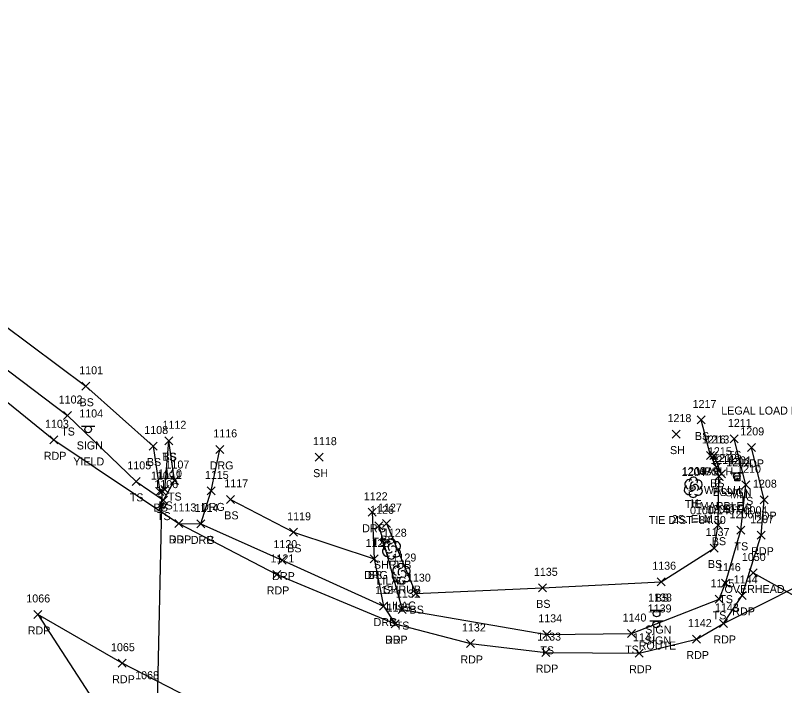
# Model space of a CAD drawing. Extents: x 1611797 to 1633212, y 298978 to 305475.
# Drawn here: x 1612037.9 to 1612230.1, y 300494.1 to 300661.6 of the extents above; entities that cross this region are included whole.
import ezdxf

# ---------------------------------------------------------------- set-up
doc = ezdxf.new("R2010")
doc.units = 0
for name, color, linetype in [('C_A', 7, 'Continuous'), ('C_C', 7, 'Continuous'), ('C_I', 7, 'Continuous'), ('CBP', 7, 'Continuous'), ('D_A', 7, 'Continuous'), ('D_C', 7, 'Continuous'), ('D_I', 7, 'Continuous'), ('D_TIC', 7, 'Continuous'), ('DCP', 7, 'Continuous'), ('DHW', 7, 'Continuous'), ('L_A', 7, 'Continuous'), ('L_C', 7, 'Continuous'), ('L_I', 7, 'Continuous'), ('L_TIC', 7, 'Continuous'), ('LELB', 7, 'Continuous'), ('LSH', 7, 'Continuous'), ('LTD', 7, 'Continuous'), ('P_A', 7, 'Continuous'), ('P_I', 7, 'Continuous'), ('P_TIC', 7, 'Continuous'), ('PET', 7, 'Continuous'), ('R_A', 7, 'Continuous'), ('R_I', 7, 'Continuous'), ('R_TIC', 7, 'Continuous'), ('RDG', 7, 'Continuous'), ('RDP', 7, 'Continuous'), ('S_A', 7, 'Continuous'), ('S_C', 7, 'Continuous'), ('S_I', 7, 'Continuous'), ('SRM', 7, 'Continuous'), ('SSGN', 7, 'Continuous'), ('U_A', 7, 'Continuous'), ('U_I', 7, 'Continuous'), ('U_TIC', 7, 'Continuous'), ('UCO', 7, 'Continuous')]:
    doc.layers.add(name, color=color, linetype=linetype)

msp = doc.modelspace()

# ---------------------------------------------------------------- linework, layer by layer
at = {"layer": 'CBP'}
for radius in [0.625, 0.0833]:
    msp.add_circle((1612207.07, 300543.45), radius, dxfattribs=at)
at = {"layer": 'D_TIC'}
for points in [[(1612211.41, 300550.59), (1612213.41, 300552.59)], [(1612213.41, 300550.59), (1612211.41, 300552.59)], [(1612212.03, 300547.65), (1612214.03, 300549.65)], [(1612214.03, 300547.65), (1612212.03, 300549.65)], [(1612213.3, 300545.96), (1612215.3, 300547.96)], [(1612215.3, 300545.96), (1612213.3, 300547.96)], [(1612073.52, 300541.7), (1612075.52, 300543.7)], [(1612075.52, 300541.7), (1612073.52, 300543.7)]]:
    msp.add_lwpolyline(points, dxfattribs=at)
at = {"layer": 'DCP'}
msp.add_lwpolyline([(1612073.27, 300485.68), (1612074.52, 300542.7)], dxfattribs=at)
at = {"layer": 'DHW'}
msp.add_lwpolyline([(1612214.3, 300546.96), (1612212.41, 300551.59)], dxfattribs=at)
at = {"layer": 'L_TIC'}
for points in [[(1612054.46, 300567.89), (1612056.46, 300569.89)], [(1612056.46, 300567.89), (1612054.46, 300569.89)], [(1612049.89, 300560.58), (1612051.89, 300562.58)], [(1612051.89, 300560.58), (1612049.89, 300562.58)], [(1612208.2, 300559.46), (1612210.2, 300561.46)], [(1612210.2, 300559.46), (1612208.2, 300561.46)], [(1612201.93, 300555.93), (1612203.93, 300557.93)], [(1612203.93, 300555.93), (1612201.93, 300557.93)], [(1612071.28, 300552.95), (1612073.28, 300554.95)], [(1612073.28, 300552.95), (1612071.28, 300554.95)], [(1612075.19, 300554.26), (1612077.19, 300556.26)], [(1612077.19, 300554.26), (1612075.19, 300556.26)], [(1612075.19, 300554.26), (1612077.19, 300556.26)], [(1612077.19, 300554.26), (1612075.19, 300556.26)], [(1612216.45, 300554.73), (1612218.45, 300556.73)], [(1612218.45, 300554.73), (1612216.45, 300556.73)], [(1612112.78, 300550.17), (1612114.78, 300552.17)], [(1612114.78, 300550.17), (1612112.78, 300552.17)], [(1612210.57, 300550.59), (1612212.57, 300552.59)], [(1612212.57, 300550.59), (1612210.57, 300552.59)], [(1612212.03, 300547.65), (1612214.03, 300549.65)], [(1612214.03, 300547.65), (1612212.03, 300549.65)], [(1612212.64, 300545.45), (1612214.64, 300547.45)], [(1612214.64, 300545.45), (1612212.64, 300547.45)], [(1612067.05, 300544.12), (1612069.05, 300546.12)], [(1612069.05, 300544.12), (1612067.05, 300546.12)], [(1612076.59, 300544.32), (1612078.59, 300546.32)], [(1612078.59, 300544.32), (1612076.59, 300546.32)], [(1612072.95, 300541.57), (1612074.95, 300543.57)], [(1612074.95, 300541.57), (1612072.95, 300543.57)], [(1612074.18, 300542.1), (1612076.18, 300544.1)], [(1612076.18, 300542.1), (1612074.18, 300544.1)], [(1612219.41, 300543.25), (1612221.41, 300545.25)], [(1612221.41, 300543.25), (1612219.41, 300545.25)], [(1612090.62, 300539.62), (1612092.62, 300541.62)], [(1612092.62, 300539.62), (1612090.62, 300541.62)], [(1612073.84, 300539.42), (1612075.84, 300541.42)], [(1612075.84, 300539.42), (1612073.84, 300541.42)], [(1612127.68, 300533), (1612129.68, 300535)], [(1612129.68, 300533), (1612127.68, 300535)], [(1612129.59, 300533.56), (1612131.59, 300535.56)], [(1612131.59, 300533.56), (1612129.59, 300535.56)], [(1612212.42, 300533.16), (1612214.42, 300535.16)], [(1612214.42, 300533.16), (1612212.42, 300535.16)], [(1612218.14, 300531.88), (1612220.14, 300533.88)], [(1612220.14, 300531.88), (1612218.14, 300533.88)], [(1612106.35, 300531.38), (1612108.35, 300533.38)], [(1612108.35, 300531.38), (1612106.35, 300533.38)], [(1612211.46, 300527.45), (1612213.46, 300529.45)], [(1612213.46, 300527.45), (1612211.46, 300529.45)], [(1612126.5, 300524.71), (1612128.5, 300526.71)], [(1612128.5, 300524.71), (1612126.5, 300526.71)], [(1612198.18, 300519.03), (1612200.18, 300521.03)], [(1612200.18, 300519.03), (1612198.18, 300521.03)], [(1612214.33, 300518.67), (1612216.33, 300520.67)], [(1612216.33, 300518.67), (1612214.33, 300520.67)], [(1612168.55, 300517.5), (1612170.55, 300519.5)], [(1612170.55, 300517.5), (1612168.55, 300519.5)], [(1612136.91, 300516.05), (1612138.91, 300518.05)], [(1612138.91, 300516.05), (1612136.91, 300518.05)], [(1612212.69, 300514.63), (1612214.69, 300516.63)], [(1612214.69, 300514.63), (1612212.69, 300516.63)], [(1612133.5, 300512.07), (1612135.5, 300514.07)], [(1612135.5, 300512.07), (1612133.5, 300514.07)], [(1612169.63, 300505.87), (1612171.63, 300507.87)], [(1612171.63, 300505.87), (1612169.63, 300507.87)], [(1612190.79, 300506.07), (1612192.79, 300508.07)], [(1612192.79, 300506.07), (1612190.79, 300508.07)]]:
    msp.add_lwpolyline(points, dxfattribs=at)
at = {"layer": 'LELB'}
for points in [[(1611964.04, 300661.61), (1611970.26, 300646.34), (1611994.83, 300618.41), (1612027.74, 300589.61), (1612055.46, 300568.89), (1612072.28, 300553.95), (1612073.95, 300542.57), (1612075.18, 300543.1), (1612076.19, 300555.26)], [(1611953.6, 300656.36), (1611964.8, 300638.56), (1611988.71, 300611.02), (1612021.99, 300583.42), (1612050.89, 300561.58), (1612068.05, 300545.12), (1612074.84, 300540.42), (1612077.59, 300545.32), (1612076.19, 300555.26)], [(1612130.59, 300534.56), (1612137.91, 300517.05), (1612169.55, 300518.5), (1612199.18, 300520.03), (1612212.46, 300528.45), (1612213.42, 300534.16), (1612213.64, 300546.45), (1612213.03, 300548.65), (1612211.57, 300551.59), (1612209.2, 300560.46)], [(1612128.68, 300534), (1612134.5, 300513.07), (1612170.63, 300506.87), (1612191.79, 300507.07), (1612213.69, 300515.63), (1612215.33, 300519.67), (1612219.14, 300532.88), (1612220.41, 300544.25), (1612217.45, 300555.73)], [(1612091.62, 300540.62), (1612107.35, 300532.38), (1612127.5, 300525.71)]]:
    msp.add_lwpolyline(points, dxfattribs=at)
at = {"layer": 'LSH'}
for p, q in [((1612131.81, 300528.28), (1612131.81, 300528.28)), ((1612131.81, 300528.28), (1612131.81, 300528.28)), ((1612134.22, 300522.08), (1612134.22, 300522.08)), ((1612134.22, 300522.08), (1612134.22, 300522.08))]:
    msp.add_line(p, q, dxfattribs=at)
for centre in [(1612131.86, 300529.71), (1612134.27, 300523.51)]:
    msp.add_arc(centre, 1.05, 335.5272, 180.9563, dxfattribs=at)
for centre, major_axis, ratio, start_param, end_param in [((1612131.02, 300528.94), (1.21, -0.51), 0.895232, 1.570796, 4.712389), ((1612132.85, 300528.86), (-1.14, -0.48), 0.949671, 1.570796, 4.712389), ((1612130.73, 300527.57), (0.58, -1.04), 0.959034, 3.141593, 6.283185), ((1612131.6, 300528.73), (-0.208, -0.792), 0.645439, 3.141593, 6.283185), ((1612132.31, 300528.11), (-0.5, 0.667), 0.989748, 3.141593, 6.283185), ((1612132.81, 300527.44), (-1.09, 0.79), 0.841452, 1.570796, 4.712389), ((1612131.81, 300526.78), (0.26, 1.06), 0.942809, 1.570796, 4.712389), ((1612131.35, 300527.53), (-0.625, -0.083), 0.423636, 0, 3.141593), ((1612133.14, 300521.37), (0.58, -1.04), 0.959034, 3.141593, 6.283185), ((1612133.43, 300522.75), (1.21, -0.51), 0.895232, 1.570796, 4.712389), ((1612134.02, 300522.54), (-0.208, -0.792), 0.645439, 3.141593, 6.283185), ((1612134.72, 300521.91), (-0.5, 0.667), 0.989748, 3.141593, 6.283185), ((1612135.27, 300522.66), (-1.14, -0.48), 0.949671, 1.570796, 4.712389), ((1612134.22, 300520.58), (0.26, 1.06), 0.942809, 1.570796, 4.712389), ((1612133.77, 300521.33), (-0.625, -0.083), 0.423636, 0, 3.141593), ((1612135.22, 300521.25), (-1.09, 0.79), 0.841452, 1.570796, 4.712389)]:
    msp.add_ellipse(centre, major_axis=major_axis, ratio=ratio, start_param=start_param, end_param=end_param, dxfattribs=at)
at = {"layer": 'LTD'}
msp.add_line((1612207.23, 300543.69), (1612207.23, 300543.69), dxfattribs=at)
msp.add_line((1612207.23, 300543.69), (1612207.23, 300543.69), dxfattribs=at)
msp.add_arc((1612207.28, 300545.12), 1.05, 335.5272, 180.9563, dxfattribs=at)
for centre, major_axis, ratio, start_param, end_param in [((1612206.44, 300544.35), (1.21, -0.51), 0.895232, 1.570796, 4.712389), ((1612208.27, 300544.27), (-1.14, -0.48), 0.949671, 1.570796, 4.712389), ((1612206.15, 300542.98), (0.58, -1.04), 0.959034, 3.141593, 6.283185), ((1612207.02, 300544.14), (-0.208, -0.792), 0.645439, 3.141593, 6.283185), ((1612207.73, 300543.52), (-0.5, 0.667), 0.989748, 3.141593, 6.283185), ((1612208.23, 300542.85), (-1.09, 0.79), 0.841452, 1.570796, 4.712389), ((1612207.23, 300542.19), (0.26, 1.06), 0.942809, 1.570796, 4.712389), ((1612206.77, 300542.94), (-0.625, -0.083), 0.423636, 0, 3.141593)]:
    msp.add_ellipse(centre, major_axis=major_axis, ratio=ratio, start_param=start_param, end_param=end_param, dxfattribs=at)
at = {"layer": 'P_TIC'}
for points in [[(1612046.48, 300554.5), (1612048.48, 300556.5)], [(1612048.48, 300554.5), (1612046.48, 300556.5)], [(1612220.78, 300552.61), (1612222.78, 300554.61)], [(1612222.78, 300552.61), (1612220.78, 300554.61)], [(1612223.94, 300539.54), (1612225.94, 300541.54)], [(1612225.94, 300539.54), (1612223.94, 300541.54)], [(1612077.69, 300533.59), (1612079.69, 300535.59)], [(1612079.69, 300533.59), (1612077.69, 300535.59)], [(1612223.22, 300530.66), (1612225.22, 300532.66)], [(1612225.22, 300530.66), (1612223.22, 300532.66)], [(1612102.17, 300520.85), (1612104.17, 300522.85)], [(1612104.17, 300520.85), (1612102.17, 300522.85)], [(1612218.49, 300515.61), (1612220.49, 300517.61)], [(1612220.49, 300515.61), (1612218.49, 300517.61)], [(1612042.48, 300510.85), (1612044.48, 300512.85)], [(1612044.48, 300510.85), (1612042.48, 300512.85)], [(1612131.73, 300508.54), (1612133.73, 300510.54)], [(1612133.73, 300508.54), (1612131.73, 300510.54)], [(1612213.78, 300508.59), (1612215.78, 300510.59)], [(1612215.78, 300508.59), (1612213.78, 300510.59)], [(1612213.78, 300508.59), (1612215.78, 300510.59)], [(1612215.78, 300508.59), (1612213.78, 300510.59)], [(1612150.57, 300503.59), (1612152.57, 300505.59)], [(1612152.57, 300503.59), (1612150.57, 300505.59)], [(1612207.02, 300504.7), (1612209.02, 300506.7)], [(1612209.02, 300504.7), (1612207.02, 300506.7)], [(1612169.38, 300501.31), (1612171.38, 300503.31)], [(1612171.38, 300501.31), (1612169.38, 300503.31)], [(1612192.74, 300501.14), (1612194.74, 300503.14)], [(1612194.74, 300501.14), (1612192.74, 300503.14)], [(1612063.58, 300498.66), (1612065.58, 300500.66)], [(1612065.58, 300498.66), (1612063.58, 300500.66)]]:
    msp.add_lwpolyline(points, dxfattribs=at)
at = {"layer": 'PET'}
for points in [[(1611938.88, 300643.49), (1611961.36, 300631.75), (1611984.86, 300608.51), (1612017.32, 300579.9), (1612047.48, 300555.5), (1612078.69, 300534.59), (1612103.17, 300521.85), (1612132.73, 300509.54), (1612151.57, 300504.59), (1612170.38, 300502.31), (1612193.74, 300502.14), (1612208.02, 300505.7), (1612214.78, 300509.59), (1612242.88, 300523.72)], [(1612214.78, 300509.59), (1612219.49, 300516.61), (1612224.22, 300531.66), (1612224.94, 300540.54), (1612221.78, 300553.61)], [(1612081.39, 300452.17), (1612099.61, 300458.97), (1612131.48, 300469.92), (1612112.83, 300476.98), (1612089.93, 300486.55), (1612064.58, 300499.66), (1612043.48, 300511.85), (1612066.24, 300476.74)]]:
    msp.add_lwpolyline(points, dxfattribs=at)
at = {"layer": 'R_TIC'}
for points in [[(1612087.93, 300552.11), (1612089.93, 300554.11)], [(1612089.93, 300552.11), (1612087.93, 300554.11)], [(1612085.76, 300541.73), (1612087.76, 300543.73)], [(1612087.76, 300541.73), (1612085.76, 300543.73)], [(1612126.03, 300536.39), (1612128.03, 300538.39)], [(1612128.03, 300536.39), (1612126.03, 300538.39)], [(1612077.69, 300533.59), (1612079.69, 300535.59)], [(1612079.69, 300533.59), (1612077.69, 300535.59)], [(1612083.22, 300533.48), (1612085.22, 300535.48)], [(1612085.22, 300533.48), (1612083.22, 300535.48)], [(1612083.22, 300533.48), (1612085.22, 300535.48)], [(1612085.22, 300533.48), (1612083.22, 300535.48)], [(1612103.55, 300524.42), (1612105.55, 300526.42)], [(1612105.55, 300524.42), (1612103.55, 300526.42)], [(1612126.5, 300524.71), (1612128.5, 300526.71)], [(1612128.5, 300524.71), (1612126.5, 300526.71)], [(1612128.88, 300512.92), (1612130.88, 300514.92)], [(1612130.88, 300512.92), (1612128.88, 300514.92)], [(1612128.88, 300512.92), (1612130.88, 300514.92)], [(1612130.88, 300512.92), (1612128.88, 300514.92)], [(1612131.73, 300508.54), (1612133.73, 300510.54)], [(1612133.73, 300508.54), (1612131.73, 300510.54)]]:
    msp.add_lwpolyline(points, dxfattribs=at)
at = {"layer": 'RDG'}
for points in [[(1612084.22, 300534.48), (1612086.76, 300542.73), (1612088.93, 300553.11)], [(1612127.03, 300537.39), (1612127.5, 300525.71), (1612129.88, 300513.92)]]:
    msp.add_lwpolyline(points, dxfattribs=at)
at = {"layer": 'RDP'}
msp.add_lwpolyline([(1612078.69, 300534.59), (1612084.22, 300534.48), (1612104.55, 300525.42), (1612129.88, 300513.92), (1612132.73, 300509.54)], dxfattribs=at)
at = {"layer": 'SRM'}
msp.add_lwpolyline([(1612217.61, 300546.51), (1612218.86, 300546.51), (1612218.86, 300545.26), (1612217.61, 300545.26)], close=True, dxfattribs=at)
msp.add_circle((1612218.24, 300545.88), 0.0833, dxfattribs=at)
at = {"layer": 'SSGN'}
for p, q in [((1612054.41, 300558.95), (1612057.75, 300558.95)), ((1612056.06, 300558.12), (1612056.06, 300558.12)), ((1612216.48, 300547.22), (1612219.81, 300547.22)), ((1612218.13, 300546.39), (1612218.13, 300546.39)), ((1612196.45, 300512.94), (1612199.78, 300512.94)), ((1612198.09, 300512.1), (1612198.09, 300512.1)), ((1612196.36, 300510.21), (1612199.7, 300510.21)), ((1612198.01, 300509.37), (1612198.01, 300509.37))]:
    msp.add_line(p, q, dxfattribs=at)
for centre in [(1612056.06, 300558.12), (1612218.13, 300546.39), (1612198.09, 300512.1), (1612198.01, 300509.37)]:
    msp.add_circle(centre, 0.833, dxfattribs=at)
at = {"layer": 'U_TIC'}
for points in [[(1612221.24, 300521.21), (1612223.24, 300523.21)], [(1612223.24, 300521.21), (1612221.24, 300523.21)]]:
    msp.add_lwpolyline(points, dxfattribs=at)
at = {"layer": 'UCO'}
msp.add_lwpolyline([(1612222.24, 300522.21), (1612272.65, 300494.16)], dxfattribs=at)

# ---------------------------------------------------------------- texts
at = {"layer": 'C_A'}
msp.add_text('TIE', height=2, dxfattribs=at).set_placement((1612205.15, 300538.45))
at = {"layer": 'C_C'}
msp.add_text('TIE DIST=84.50', height=2, dxfattribs=at).set_placement((1612196.12, 300534.45))
at = {"layer": 'C_I'}
msp.add_text('1204', height=2, dxfattribs=at).set_placement((1612204.3, 300546.45))
at = {"layer": 'D_A'}
for s, p in [('WALLH', (1612208, 300546.59)), ('P', (1612212.41, 300543.65)), ('WALLH', (1612209.89, 300541.96)), ('P', (1612073.9, 300537.7))]:
    msp.add_text(s, height=2, dxfattribs=at).set_placement(p)
at = {"layer": 'D_C'}
msp.add_text('MARBLE', height=2, dxfattribs=at).set_placement((1612208.85, 300537.96))
at = {"layer": 'D_I'}
for s, p in [('1213', (1612210.29, 300554.59)), ('1215', (1612210.9, 300551.65)), ('1212', (1612212.17, 300549.96)), ('1111', (1612073.53, 300545.7))]:
    msp.add_text(s, height=2, dxfattribs=at).set_placement(p)
at = {"layer": 'L_A'}
for s, p in [('BS', (1612053.9, 300563.89)), ('TS', (1612049.3, 300556.58)), ('BS', (1612207.64, 300555.46)), ('SH', (1612201.42, 300551.93)), ('TS', (1612074.6, 300550.26)), ('BS', (1612074.63, 300550.26)), ('TS', (1612215.86, 300550.73)), ('BS', (1612070.72, 300548.95)), ('SH', (1612112.27, 300546.17)), ('BS', (1612210.01, 300546.59)), ('BS', (1612211.47, 300543.65)), ('BS', (1612212.08, 300541.45)), ('TS', (1612066.46, 300540.12)), ('TS', (1612076, 300540.32)), ('BS', (1612072.39, 300537.57)), ('BS', (1612073.62, 300538.1)), ('H', (1612206.66, 300538.69)), ('TS', (1612218.82, 300539.25)), ('BS', (1612090.06, 300535.62)), ('TS', (1612073.25, 300535.42)), ('TS', (1612127.09, 300529)), ('BS', (1612129.03, 300529.56)), ('BS', (1612211.86, 300529.16)), ('BS', (1612105.79, 300527.38)), ('TS', (1612217.55, 300527.88)), ('SHRUB', (1612127.44, 300523.28)), ('BS', (1612210.9, 300523.45)), ('BS', (1612125.94, 300520.71)), ('SHRUB', (1612129.85, 300517.08)), ('BS', (1612197.62, 300515.03)), ('TS', (1612213.74, 300514.67)), ('BS', (1612167.99, 300513.5)), ('BS', (1612136.35, 300512.05)), ('TS', (1612212.09, 300510.63)), ('TS', (1612132.9, 300508.07)), ('TS', (1612169.04, 300501.87)), ('TS', (1612190.2, 300502.07))]:
    msp.add_text(s, height=2, dxfattribs=at).set_placement(p)
at = {"layer": 'L_C'}
for s, p in [('2S. ELM', (1612201.88, 300534.69)), ('LILAC', (1612128.09, 300519.28)), ('LILAC', (1612130.5, 300513.08))]:
    msp.add_text(s, height=2, dxfattribs=at).set_placement(p)
at = {"layer": 'L_I'}
for s, p in [('1101', (1612053.82, 300571.89)), ('1102', (1612048.69, 300564.58)), ('1217', (1612207.07, 300563.46)), ('1218', (1612200.81, 300559.93)), ('1211', (1612215.89, 300558.73)), ('1108', (1612070.08, 300556.95)), ('1112', (1612074.63, 300558.26)), ('1112', (1612074.63, 300558.26)), ('1118', (1612112.22, 300554.17)), ('1216', (1612209.39, 300554.59)), ('1215', (1612210.9, 300551.65)), ('1214', (1612211.52, 300549.45)), ('1105', (1612065.85, 300548.12)), ('1107', (1612075.38, 300548.32)), ('1210', (1612218.2, 300547.25)), ('1109', (1612071.74, 300545.57)), ('1110', (1612073.54, 300546.1)), ('1203', (1612204.46, 300546.69)), ('1106', (1612072.58, 300543.42)), ('1117', (1612090.07, 300543.62)), ('1127', (1612128.47, 300537.56)), ('1126', (1612126.5, 300537)), ('1205', (1612210.65, 300537.16)), ('1206', (1612216.31, 300535.88)), ('1119', (1612105.78, 300535.38)), ('1128', (1612129.69, 300531.28)), ('1137', (1612210.33, 300531.45)), ('1123', (1612125.37, 300528.71)), ('1129', (1612132.09, 300525.08)), ('1136', (1612196.99, 300523.03)), ('1146', (1612213.15, 300522.67)), ('1135', (1612167.42, 300521.5)), ('1130', (1612135.7, 300520.05)), ('1145', (1612211.56, 300518.63)), ('1131', (1612132.94, 300516.07)), ('1134', (1612168.51, 300509.87)), ('1140', (1612189.58, 300510.07)), ('1068', (1612067.79, 300495.65)), ('1068', (1612067.79, 300495.65))]:
    msp.add_text(s, height=2, dxfattribs=at).set_placement(p)
at = {"layer": 'P_A'}
for p in [(1612044.97, 300550.5), (1612219.27, 300548.61), (1612222.42, 300535.54), (1612076.18, 300529.59), (1612221.71, 300526.66), (1612100.66, 300516.85), (1612216.98, 300511.61), (1612040.96, 300506.85), (1612130.22, 300504.54), (1612212.27, 300504.59), (1612212.27, 300504.59), (1612149.06, 300499.59), (1612205.51, 300500.7), (1612167.87, 300497.31), (1612191.23, 300497.14), (1612062.06, 300494.66)]:
    msp.add_text('RDP', height=2, dxfattribs=at).set_placement(p)
at = {"layer": 'P_I'}
for s, p in [('1103', (1612045.28, 300558.5)), ('1209', (1612219, 300556.61)), ('1208', (1612222.16, 300543.54)), ('1113', (1612077.13, 300537.59)), ('1207', (1612221.45, 300534.66)), ('1121', (1612101.61, 300524.85)), ('1144', (1612217.36, 300519.61)), ('1066', (1612040.6, 300514.85)), ('1125', (1612130.6, 300512.54)), ('1143', (1612212.66, 300512.59)), ('1143', (1612212.66, 300512.59)), ('1142', (1612205.9, 300508.7)), ('1132', (1612149.45, 300507.59)), ('1133', (1612168.25, 300505.31)), ('1141', (1612192.18, 300505.14)), ('1065', (1612061.76, 300502.66))]:
    msp.add_text(s, height=2, dxfattribs=at).set_placement(p)
at = {"layer": 'R_A'}
for s, p in [('DRG', (1612086.42, 300548.11)), ('DRG', (1612084.25, 300537.73)), ('DRG', (1612124.52, 300532.39)), ('DRP', (1612076.18, 300529.59)), ('DRG', (1612081.71, 300529.48)), ('DRP', (1612081.71, 300529.48)), ('DRP', (1612102.04, 300520.42)), ('DRG', (1612124.99, 300520.71)), ('DRG', (1612127.37, 300508.92)), ('DRP', (1612127.37, 300508.92)), ('DRP', (1612130.22, 300504.54))]:
    msp.add_text(s, height=2, dxfattribs=at).set_placement(p)
at = {"layer": 'R_I'}
for s, p in [('1116', (1612087.32, 300556.11)), ('1115', (1612085.21, 300545.73)), ('1122', (1612124.91, 300540.39)), ('1113', (1612077.13, 300537.59)), ('1114', (1612082.66, 300537.48)), ('1114', (1612082.66, 300537.48)), ('1120', (1612102.34, 300528.42)), ('1123', (1612125.37, 300528.71)), ('1124', (1612127.75, 300516.92)), ('1124', (1612127.75, 300516.92)), ('1125', (1612130.6, 300512.54))]:
    msp.add_text(s, height=2, dxfattribs=at).set_placement(p)
at = {"layer": 'S_A'}
for s, p in [('SIGN', (1612053.2, 300553.09)), ('SIGN', (1612215.26, 300541.37)), ('MM', (1612216.43, 300540.88)), ('SIGN', (1612195.23, 300507.08)), ('SIGN', (1612195.15, 300504.35))]:
    msp.add_text(s, height=2, dxfattribs=at).set_placement(p)
at = {"layer": 'S_C'}
for s, p in [('LEGAL LOAD LIMIT 24000 POUNDS', (1612214.24, 300561.81)), ('YIELD', (1612052.33, 300549.09)), ('0100/1407/0004', (1612206.43, 300536.88)), ('STOP', (1612214.59, 300537.37)), ('ROUTE', (1612193.6, 300503.08))]:
    msp.add_text(s, height=2, dxfattribs=at).set_placement(p)
at = {"layer": 'S_I'}
for s, p in [('1104', (1612053.83, 300561.09)), ('1201', (1612215.9, 300549.37)), ('1202', (1612215.47, 300548.88)), ('1138', (1612195.95, 300515.08)), ('1139', (1612195.86, 300512.35))]:
    msp.add_text(s, height=2, dxfattribs=at).set_placement(p)
at = {"layer": 'U_A'}
msp.add_text('OVERHEAD', height=2, dxfattribs=at).set_placement((1612215.05, 300517.21))
at = {"layer": 'U_I'}
msp.add_text('1050', height=2, dxfattribs=at).set_placement((1612219.38, 300525.21))

doc.saveas('drawing.dxf')
